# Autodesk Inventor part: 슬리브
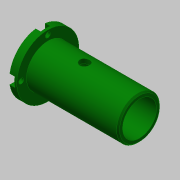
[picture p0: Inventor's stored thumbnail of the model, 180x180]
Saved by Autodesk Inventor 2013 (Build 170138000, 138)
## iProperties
Created: 2019-10
Part Number: 슬리브
Material: 알루미늄 6061
Document SubType Name: Modeling
Designer: mduedu
Density: 1 g/cm^3
Author: mduedu
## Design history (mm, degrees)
sketch "스케치1"
  geometry: L1 (0, 0)-(5, 0); L2 (5, 0)-(5, 21); L3 (5, 21)-(0, 21); L4 (0, 21)-(0, 0); L5 (5, 0)-(67, 0); L6 (67, 0)-(67, 14.5); L7 (67, 14.5)-(5, 14.5); L8 (5, 14.5)-(5, 0)
  constraints: 16 end point, 4 parallel, 2 horizontal, 2 perpendicular
  dimensions: "d0" = 67 distance between parallel lines of L6 L4; "d2" = 62 distance of L6.end L7.end; "d3" = 42 diameter of L3 L1; "d4" = 29 diameter of L7 L5
revolve "회전1" sketch "스케치1" stored, may be unused: angle "d5" = 90 deg
hole "구멍1" diameter "d8" = 23; stored, may be unused: countersink angle "d12" = 90 deg, drill point angle "d14" = 118 deg; dims "d6" = 10, "d7" = 10, "d9" = 6, "d10" = 4, "d11" = 2, "d13" = 8
sketch "스케치2"
  geometry: L1 (-5, 21)-(-5, -21) reference; C1 r 3.3 at (-30, 0); 1 further point
  constraints: 1 centre point, 1 horizontal alignment
  dimensions: "d15" = 6.6 diameter of C1; "d16" = 25 distance from line of C1.centre L1
extrude "돌출1" cut sketch "스케치2" stored distance "d17" = 10; taper "d18" = 0 deg
chamfer "모따기1" distance "d19" = 1; stored, may be unused: second distance "d20" = 2, angle "d21" = 45 deg
sketch "스케치3" dims "d22" = 36
  geometry: 6 further points
  constraints: 2 vertical alignment, 1 coincident, 7 other
  dimensions: "d25" = 360 deg dimension on point (0, 0) point (0, 18) (derived)
sketch "스케치4"
  geometry: 4 further points
  constraints: 4 other
hole "구멍2" sketch "스케치4" at (-18, 0), (0, -18), (18, 0), (0, 18) diameter "d27" = 3.4; stored, may be unused: countersink angle "d31" = 90 deg, drill point angle "d33" = 0 deg; dims "d28" = 6, "d29" = 6.5, "d30" = 3.4, "d32" = 8
sketch "스케치5"
  geometry: L1 (-21.25, 20.747)-(-21.25, 18); L2 (-14.75, 18)-(-14.75, 20.747); A1 r 3.25 centre (-18, 18) between (-19.349, 20.957) and (-16.651, 20.957) reference; A2 r 21 centre (-18, 0) between (-19.349, 20.957) and (-38.957, 1.349) reference; A3 r 21 centre (-18, 0) between (2.957, 1.349) and (-16.651, 20.957) reference; A4 r 21 centre (-18, 0) between (-14.75, 20.747) and (-21.25, 20.747); A5 r 3.25 centre (-18, 18) between (-21.25, 18) and (-14.75, 18); 1 further point
  constraints: 8 point on circle, 4 end point, 2 centre point, 2 coincident, 2 tangent, 1 parallel, 1 vertical
extrude "돌출2" cut sketch "스케치5" stored distance "d34" = 10; taper "d35" = 0 deg
node "솔리드1"
pattern_circular "원형 패턴1" dims angle "d37" = 360 deg
